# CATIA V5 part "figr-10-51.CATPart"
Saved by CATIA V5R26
Part number: Part1
Bounding box of the stored display mesh (mm): x -68.386 to 32.095, y 0 to 344, z -0.079 to 67.481
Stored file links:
  D:\_Deepak\CATIA\CATIA V5-6R2016_Deepak\Resources\Part files\Partfiles\c10_catia_v5_6r2016_prt\figr-10-51.CATPart
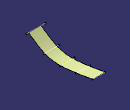
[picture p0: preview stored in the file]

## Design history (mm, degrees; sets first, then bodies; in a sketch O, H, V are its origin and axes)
Body1 (main body)
  Plane1: type Offset, RefPlane zx-plane, Offset 86
  Plane2: type Offset, RefPlane Plane1, Offset 86
  Plane3: type Offset, RefPlane Plane2, Offset 86
  Plane4: type Offset, RefPlane Plane3, Offset 86
  Sketch1 on zx-plane, origin (0, 0, 0), H (-1, 0, 0), V (0, 0, 1)
    line L1 (-32.0954, 67.4806) -> (68.3859, 67.4806)
    horizontal: L1 H
  Sketch2 on Plane1, origin (0, 86, 0), H (-1, 0, 0), V (0, 0, 1)
    line L1 (-24.4409, 14.2252) -> (55.9283, 14.2252)
    horizontal: L1 H
  Sketch3 on Plane2, origin (0, 172, 0), H (-1, 0, 0), V (0, 0, 1)
    line L1 (-24.2042, 0) -> (53.3039, 0)
    point P1 (-24.2042, 0)
    coincidence: P1 H
    horizontal: L1 H
  Sketch4 on Plane3, origin (0, 258, 0), H (-1, 0, 0), V (0, 0, 1)
    line L1 (-23.6533, 8.5985) -> (50.1324, 8.5985)
    horizontal: L1 H
  Sketch5 on Plane4, origin (0, 344, 0), H (-1, 0, 0), V (0, 0, 1)
    line L1 (-20.9465, 23.2339) -> (46.0713, 23.2339)
    horizontal: L1 H
  Sweep1: type Conic, Guide (Sketch1; Sketch2; Sketch3; Sketch4; Sketch5)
